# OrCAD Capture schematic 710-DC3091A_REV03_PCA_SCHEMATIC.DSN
size Custom; title: 5V, DUAL 6A SYNCHRONOUS STEP-DOWN REGULATOR
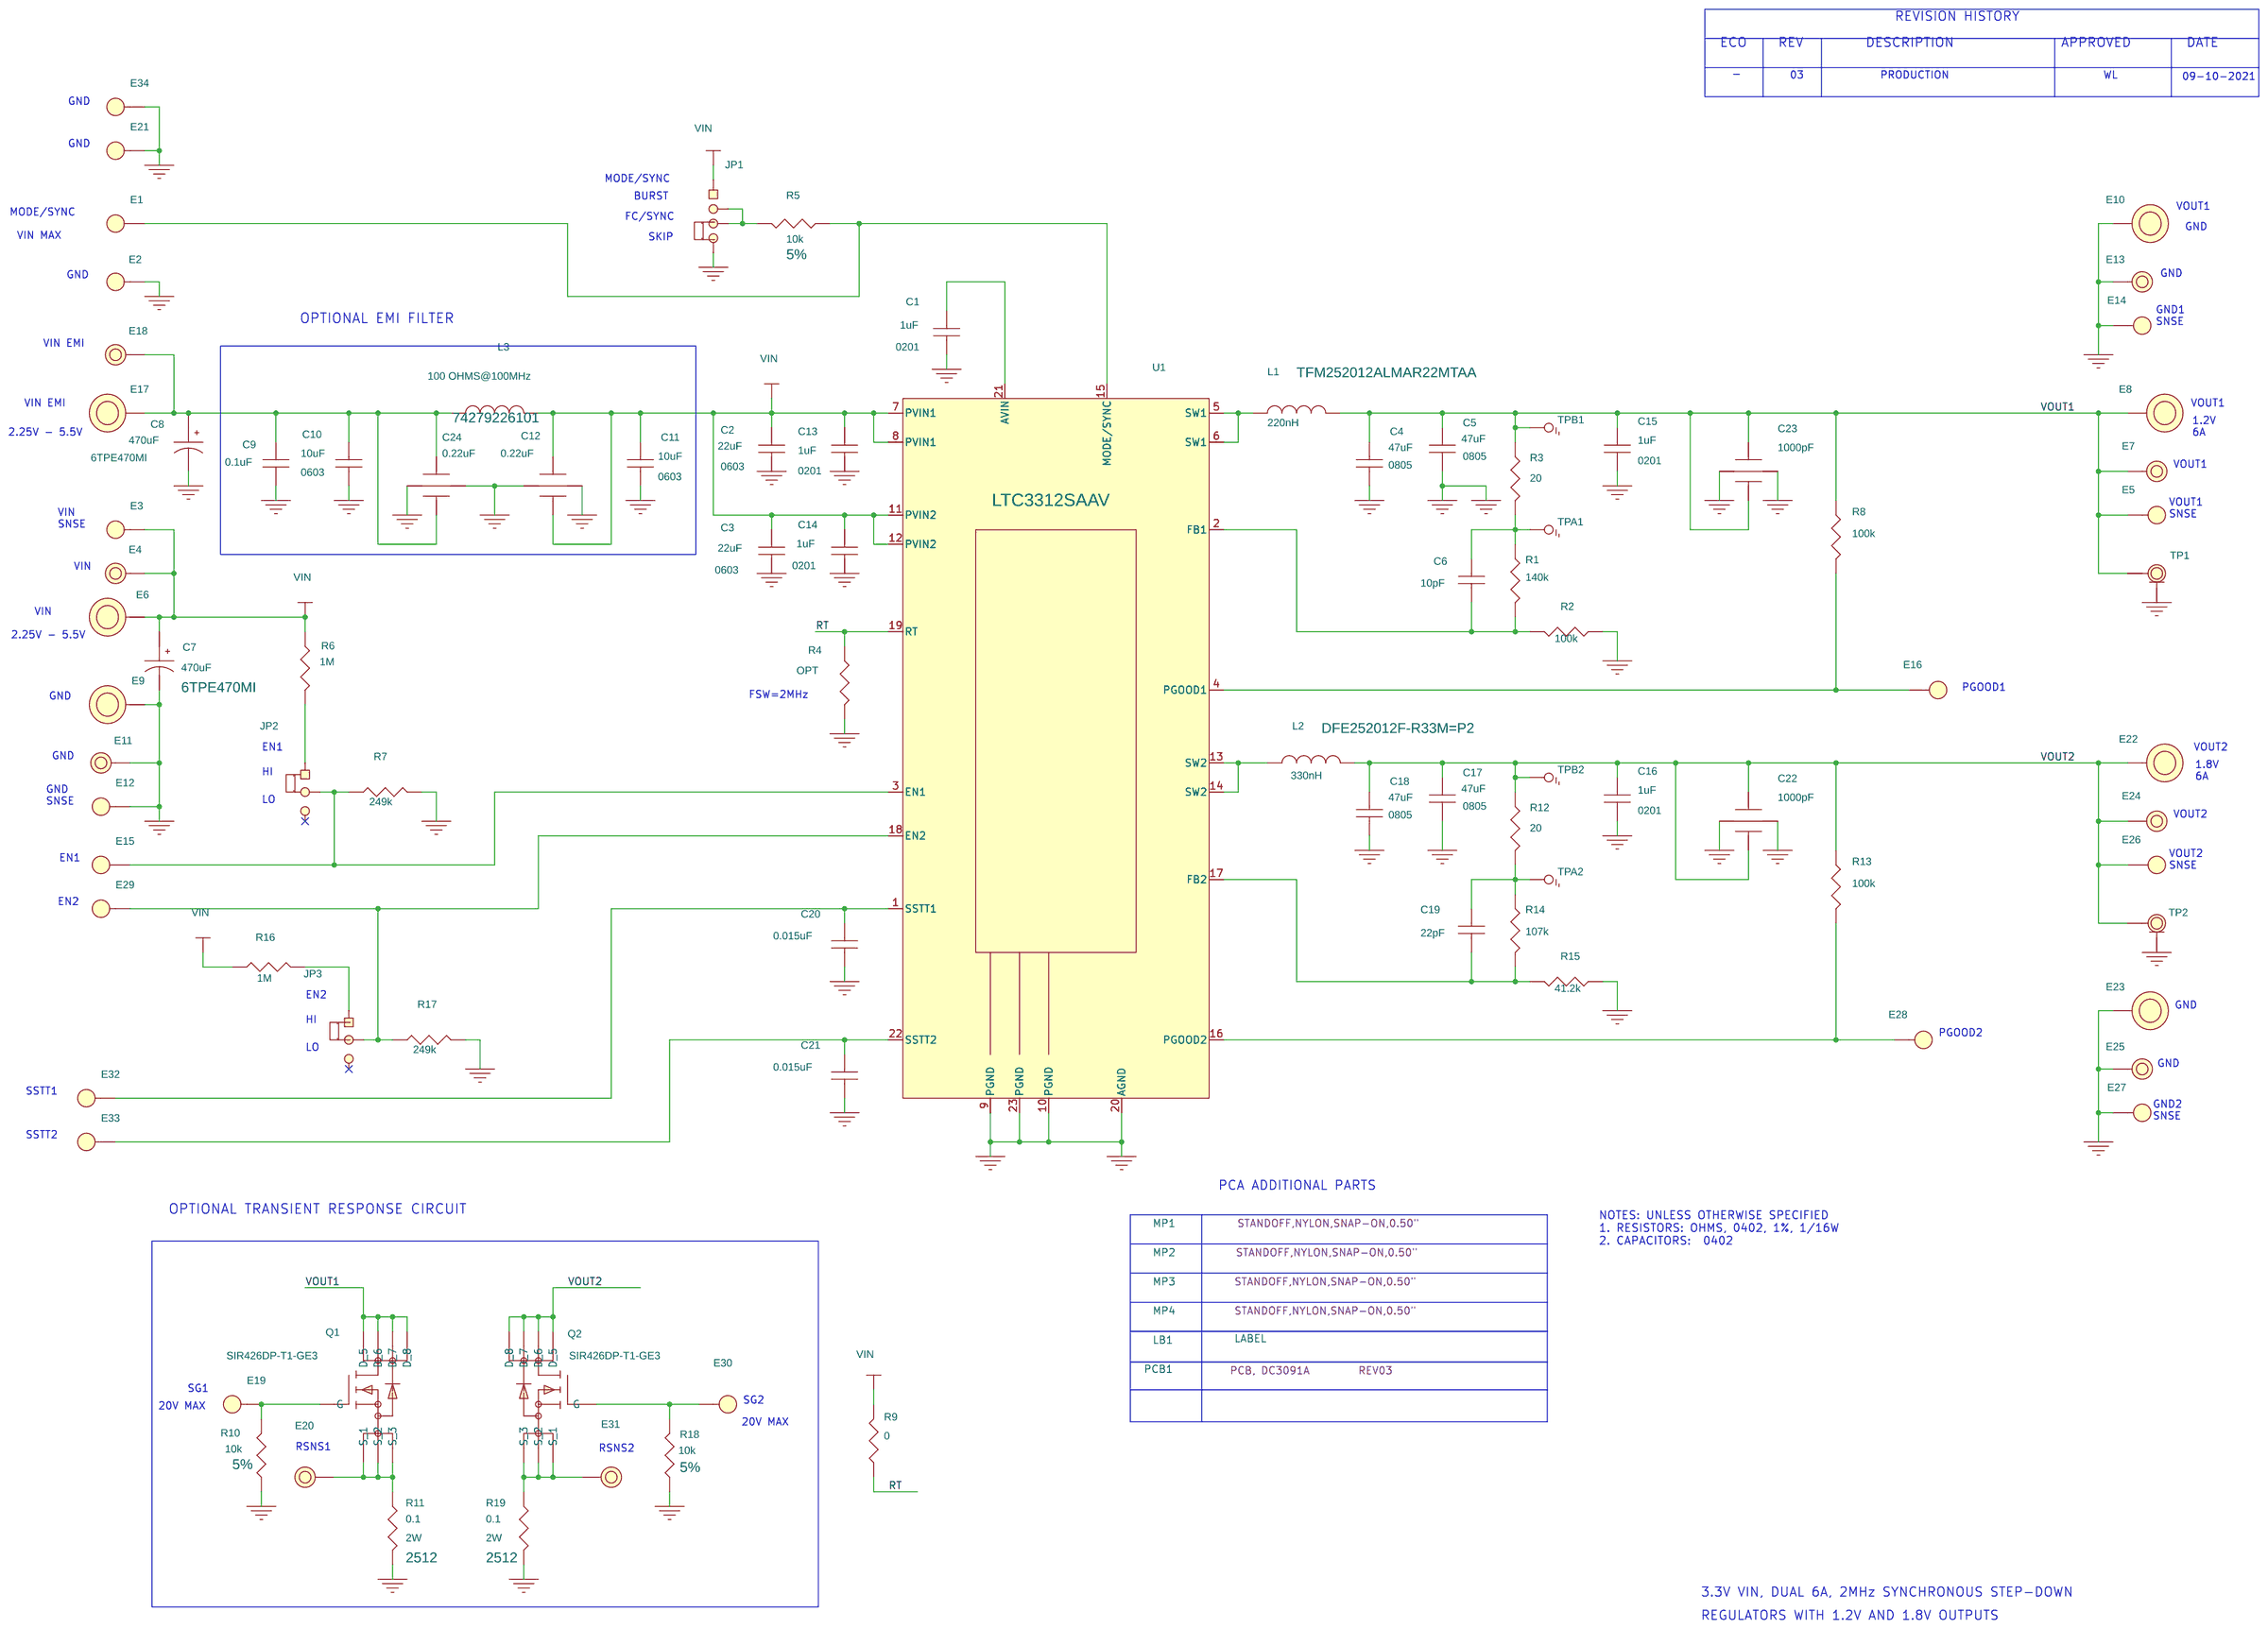
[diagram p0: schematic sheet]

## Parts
C1  1uF  [CC0201M]
C2  22uF  [CC0603N]
C3  22uF  [CC0603N]
C4  47uF  [CC0805L]
C5  47uF  [CC0805L]
C6  10pF  [CC0402N]
C7  470uF  [CAPMP7343N]
C8  470uF  [CAPMP7343N]
C9  0.1uF  [CC0402N]
C10  10uF  [CC0603N]
C11  10uF  [CC0603N]
C12  0.22uF  [JOHANSON-X2Y-X14]
C13  1uF  [CC0201M]
C14  1uF  [CC0201M]
C15  1uF  [CC0201M]
C16  1uF  [CC0201M]
C17  47uF  [CC0805L]
C18  47uF  [CC0805L]
C19  22pF  [CC0402N]
C20  0.015uF  [CC0402N]
C21  0.015uF  [CC0402N]
C22  1000pF  [JOHANSON-X2Y-X07]
C23  1000pF  [JOHANSON-X2Y-X07]
C24  0.22uF  [JOHANSON-X2Y-X14]
E1  TEST POINT  [MILLMAX2308]
E2  TEST POINT  [MILLMAX2308]
E3  TEST POINT  [MILLMAX2308]
E4  TEST POINT  [MILLMAX2501]
E5  TEST POINT  [MILLMAX2308]
E6  BANANA JACK  [KEY-575-4]
E7  TEST POINT  [MILLMAX2501]
E8  BANANA JACK  [KEY-575-4]
E9  BANANA JACK  [KEY-575-4]
E10  BANANA JACK  [KEY-575-4]
E11  TEST POINT  [MILLMAX2501]
E12  TEST POINT  [MILLMAX2308]
E13  TEST POINT  [MILLMAX2501]
E14  TEST POINT  [MILLMAX2308]
E15  TEST POINT  [MILLMAX2308]
E16  TEST POINT  [MILLMAX2308]
E17  BANANA JACK  [KEY-575-4]
E18  TEST POINT  [MILLMAX2501]
E19  TEST POINT  [MILLMAX2308]
E20  TEST POINT  [MILLMAX2501]
E21  TEST POINT  [MILLMAX2308]
E22  BANANA JACK  [KEY-575-4]
E23  BANANA JACK  [KEY-575-4]
E24  TEST POINT  [MILLMAX2501]
E25  TEST POINT  [MILLMAX2501]
E26  TEST POINT  [MILLMAX2308]
E27  TEST POINT  [MILLMAX2308]
E28  TEST POINT  [MILLMAX2308]
E29  TEST POINT  [MILLMAX2308]
E30  TEST POINT  [MILLMAX2308]
E31  TEST POINT  [MILLMAX2501]
E32  TEST POINT  [MILLMAX2308]
E33  TEST POINT  [MILLMAX2308]
E34  TEST POINT  [MILLMAX2308]
JP1  HDR  [JP4X1/079]
JP2  HDR  [HD1X3-079]
JP3  HDR  [HD1X3-079]
L1  220nH  [TDK-TFM252012ALMA]
L2  330nH  [MURATA-DFE252012F]
L3  100 OHMS@100MHz  [WURTH-74279226101]
LB1  LABEL  [895-0154_REV01]
MP1  STANDOFF  [KEYSTONE_8829-8834]
MP2  STANDOFF  [KEYSTONE_8829-8834]
MP3  STANDOFF  [KEYSTONE_8829-8834]
MP4  STANDOFF  [KEYSTONE_8829-8834]
PCB1  PCB, DC3091A
Q1  SIR426DP-T1-GE3  [VISHAY_PPAK_SO-8]
Q2  SIR426DP-T1-GE3  [VISHAY_PPAK_SO-8]
R1  140k  [CR0402N]
R2  100k  [CR0402N]
R3  20  [CR0402N]
R4  OPT  [CR0402N]
R5  10k  [CR0402N]
R6  1M  [CR0402N]
R7  249k  [CR0402N]
R8  100k  [CR0402N]
R9  0  [CR0402N]
R10  10k  [CR0402N]
R11  0.1  [CR2512N]
R12  20  [CR0402N]
R13  100k  [CR0402N]
R14  107k  [CR0402N]
R15  41.2k  [CR0402N]
R16  1M  [CR0402N]
R17  249k  [CR0402N]
R18  10k  [CR0402N]
R19  0.1  [CR2512N]
TP1  U.FL  [HIROSE-FL-R-SMT-1]
TP2  U.FL  [HIROSE-FL-R-SMT-1]
TPA1  COPPER FEATURE PAD  [PADSTYLE1]
TPA2  COPPER FEATURE PAD  [PADSTYLE1]
TPB1  COPPER FEATURE PAD  [PADSTYLE1]
TPB2  COPPER FEATURE PAD  [PADSTYLE1]
U1  LTC3312SAAV  [LTC-LQFN-22-7012]
XJP1  SHUNT
XJP2  SHUNT
XJP3  SHUNT

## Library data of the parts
C1 C13-C16 = CAP: CAP.,1uF,X7T,6.3V,20%,0201; CLASS: DISCRETE; Dielectric Type: X7T; FPLIST: CC0201N,CC0201L,CC0201M; Inventory Qty: 15600; Manufacturer: MURATA; Manufacturer PN: GRM033D70J105ME01D; PART_NUMBER: 150-1771; Package Size: 0201; Rated Voltage: 6.3V; Tolerance: 20%
C2 C3 = CAP: CAP.,22uF,X5R,10V,20%,0603; CLASS: DISCRETE; Dielectric Type: X5R; FPLIST: CC0603N,CC0603L,CC0603M; Inventory Qty: 29342; Manufacturer: AVX; Manufacturer PN: 0603ZD226MAT2A; PART_NUMBER: 150-2341; Package Size: 0603; Package Type: Surface Mount, MLCC; Rated Voltage: 10V; Temperature Coefficient: X5R; Tolerance: 20%
C4 C5 C17 C18 = CAP: CAP.,47uF,X6S,6.3V,20%,0805; CLASS: DISCRETE; Dielectric Type: X6S; FPLIST: CC0805L,CC0805N,CC0805M; Inventory Qty: 7800; Manufacturer: Taiyo Yuden; Manufacturer PN: JMK212BC6476MG-T; PART_NUMBER: 150-1772; Package Size: 0805; Rated Voltage: 6.3V; Temperature Coefficient: X6S; Tolerance: 20%
C6 = CAP: CAP.,10pF,C0G/NP0,50V,+/-0.5pF,0402; CLASS: DISCRETE; Dielectric Type: C0G/NP0; FPLIST: CC0402N,CC0402L,CC0402M; Inventory Qty: 24344; Manufacturer: AVX; Manufacturer PN: 04025A100DAT2A; PART_NUMBER: 150-2020; Package Size: 0402; Rated Voltage: 50V; Tolerance: +/-0.5pF
C7 C8 = CAP_P_ALT: CAP.,470uF,TANT,POSCAP,6.3V,20%,7343,18mOHMS,TPE; CLASS: DISCRETE; Dielectric Type: TANT,POSCAP; FPLIST: CAPMP7343N,CAPMP7343L,CAPMP7343M; Inventory Qty: 9794; Manufacturer: PANASONIC; Manufacturer PN: 6TPE470MI; PART_NUMBER: 150-0223; Package Size: 7343; Rated Voltage: 6.3V; Tolerance: 20%; UserField01: 2400mAms, 25mOHMS
C9 = CAP: CAP.,0.1uF,X7R,25V,10%,0402,AEC-Q200; CLASS: DISCRETE; Dielectric Type: X7R; FPLIST: CC0402N,CC0402L,CC0402M; Inventory Qty: 22030; Manufacturer: MURATA; Manufacturer PN: GCM155R71E104KE02D; PART_NUMBER: 150-1756; Package Size: 0402; Rated Voltage: 25V; Temperature Coefficient: X7R; Tolerance: 10%
C10 C11 = CAP: CAP.,10uF,X7S,6.3V,20%,0603; CLASS: DISCRETE; Dielectric Type: X7S; FPLIST: CC0603N,CC0603L,CC0603M; Inventory Qty: 34800; Manufacturer: TDK; Manufacturer PN: C1608X7S0J106M080AC; PART_NUMBER: 150-1745; Package Size: 0603; Rated Voltage: 6.3V; Tolerance: 20%
C12 C24 = JOHANSON-X2Y: CAP.,0.22uF,X7R,6.3V,20%,0603; CLASS: DISCRETE; Dielectric Type: X7R; Inventory Qty: 12000; Manufacturer: JOHANSON DIELECTRICS; Manufacturer PN: 6R3X14W224MV4T; PART_NUMBER: 150-0876; Package Size: 0603; Rated Voltage: 6.3V; Temperature Coefficient: X7R; Tolerance: 20%
C19 = CAP: CAP.,22pF,C0G,50V,10%,0402; CLASS: DISCRETE; Dielectric Type: C0G; FPLIST: CC0402N,CC0402L,CC0402M; Inventory Qty: 20000; Manufacturer: AVX; Manufacturer PN: 04025A220KAT2A; PART_NUMBER: 150-3390; Package Size: 0402; Rated Voltage: 50V; Tolerance: 10%
C20 C21 = CAP: CAP.,0.015uF,X7R,16V,10%,0402; CLASS: DISCRETE; Dielectric Type: X7R; FPLIST: CC0402N,CC0402L,CC0402M; Inventory Qty: 30000; Manufacturer: AVX; Manufacturer PN: 0402YC153KAT2A; PART_NUMBER: 150-2639; Package Size: 0402; Package Type: SMD; Rated Voltage: 16V; Tolerance: 10%
C22 C23 = JOHANSON-X2Y: CAP.,1000pF,X7R,50V,20%,0402,3-TERM,X2Y EMI FILTER; CLASS: DISCRETE; Dielectric Type: X7R; Inventory Qty: 16829; Manufacturer: JOHANSON DIELECTRICS; Manufacturer PN: 500X07W102MV4T; PART_NUMBER: 150-1785; Package Size: 0402,3-TERM; Rated Voltage: 50V; Tolerance: 20%
E1-E3 E5 E12 E14-E16 E19 E21 E26-E30 E32-E34 = TEST_POINT_.156_MILL-MAX_2308: TEST POINT,TURRET,0.064" MTG. HOLE,PCB 0.062" THK; CLASS: IO; Inventory Qty: 1142083; Manufacturer PN: 2308-2-00-80-00-00-07-0; PART_NUMBER: 260-0004
E4 E7 E11 E13 E18 E20 E24 E25 E31 = TESTPOINT_.219_MILL-MAX_2501: TEST POINT,TURRET,0.094" MTG. HOLE,PCB 0.062" THK; CLASS: IO; Inventory Qty: 823526; Manufacturer: MILL-MAX; Manufacturer PN: 2501-2-00-80-00-00-07-0; PART_NUMBER: 260-0003
E6 E8-E10 E17 E22 E23 = BANANA_KEYSTONE-575-4: CONN.,BANANA JACK,FEMALE,THT,NON-INSULATED,SWAGE,0.218"; CLASS: IO; Inventory Qty: 203061; Manufacturer: KEYSTONE; Manufacturer PN: 575-4; PART_NUMBER: 250-0428
JP1 = HD1X4-079_ALT: CONN.,HDR,MALE,1x4,2mm,VERT,ST,THT; CLASS: IO; Inventory Qty: 12591; Manufacturer: WURTH ELEKTRONIK; Manufacturer PN: 62000411121; PART_NUMBER: 250-0563
JP2 JP3 = 3_PIN_HEADER_.079_SINGLE_ROW_D: CONN.,HDR,MALE,1x3,2mm,VERT,ST,THT; CLASS: IO; Inventory Qty: 22026; Manufacturer: Wurth Elektronik; Manufacturer PN: 62000311121; PART_NUMBER: 250-0484
L1 = IND_ALT: IND.,220nH,PWR,20%,6.7A,13mOHMS,SMD,2.50mm x 2.00mm,AEC-Q200; CLASS: DISCRETE; Inventory Qty: 0; Manufacturer: TDK; Manufacturer PN: TFM252012ALMAR22MTAA; PART_NUMBER: 200-0414; Package Size: SMD,2.50mm x 2.00mm; Tolerance: 20%
L2 = IND_ALT: IND.,330nH,PWR,20%,5.1A,19mOHMS,1008; CLASS: DISCRETE; Inventory Qty: 3000; Manufacturer: MURATA; Manufacturer PN: DFE252012F-R33M=P2; PART_NUMBER: 200-0394; Package Size: 1008; Tolerance: 20%
L3 = IND_ALT: IND.,100 OHMS@100MHz,FERRITE BEAD,25%,8A,6mOHMS,1812; CLASS: DISCRETE; Inventory Qty: 3043; Manufacturer: WURTH ELEKTRONIK; Manufacturer PN: 74279226101; PART_NUMBER: 200-0280; Package Size: 1812; Tolerance: 25%
LB1 = BLANK_LABEL: LABEL SPEC, DEMO BOARD SERIAL NUMBER; Inventory Qty: 0; Manufacturer: BRADY; Manufacturer PN: THT-96-717-10; PART_NUMBER: 895-0154
MP1-MP4 = BLANK_MECHANICAL_PART: STANDOFF,NYLON,SNAP-ON,0.50"; CLASS: DISCRETE; FPLIST: KEYSTONE_8829-8834,MTG-8831; Inventory Qty: 9249; Manufacturer: WURTH ELEKTRONIK; Manufacturer PN: 702935000; PART_NUMBER: 763-0020
PCB1 = BLANK_PCB_PART: BOM Notes: REV03; CLASS: DISCRETE; Inventory Qty: 0; Manufacturer: ADI APPROVED SUPPLIER; Manufacturer PN: 600-DC3091A; PART_NUMBER: 600-DC3091A
Q1 Q2 = 8P_N-CH_TYPE1A: XSTR.,MOSFET,N-CH,40V,15.9A,PPAK SO-8; CLASS: DISCRETE; Inventory Qty: 20200; Manufacturer: VISHAY; PART_NUMBER: 240-0378; Package Size: PowerPAK® SO-8; Package Type: PPAK SO-8; Polarity: MOSFET N-Channel; Rated Power: 41.7W; Rated Voltage: 40V
R1 = RES: RES.,140k OHMS,1%,1/16W,0402,AEC-Q200; CLASS: DISCRETE; FPLIST: CR0402N,CR0402L,CR0402M; Inventory Qty: 70827; Manufacturer: NIC; Manufacturer PN: NRC04F1403TRF; PART_NUMBER: 100-2880; Package Size: 0402; Rated Power: 1/16W; Temperature Coefficient: 100ppm; Tolerance: 1%
R2 = RES: RES.,100k OHMS,1%,1/16W,0402,AEC-Q200; CLASS: DISCRETE; FPLIST: CR0402N,CR0402L,CR0402M; Inventory Qty: 150967; Manufacturer: VISHAY; Manufacturer PN: CRCW0402100KFKED; PART_NUMBER: 100-2396; Package Size: 0402; Rated Power: 1/16W; Temperature Coefficient: 100ppm; Tolerance: 1%
R3 R12 = RES: RES.,20 OHMS,1%,1/16W,0402,AEC-Q200; CLASS: DISCRETE; FPLIST: CR0402N,CR0402L,CR0402M; Inventory Qty: 29845; Manufacturer: NIC; Manufacturer PN: NRC04F20R0TRF; PART_NUMBER: 100-0250; Package Size: 0402; Rated Power: 1/16W; Temperature Coefficient: 100ppm; Tolerance: 1%
R4 = RES: RES., OPTION, 0402; CLASS: DISCRETE; FPLIST: CR0402N,CR0402L,CR0402M; PART_NUMBER: 100-0357; Package Size: 0402
R5 R10 R18 = RES: RES.,10k OHMS,5%,1/10W,0402,AEC-Q200; CLASS: DISCRETE; FPLIST: CR0402N,CR0402L,CR0402M; Inventory Qty: 33211; Manufacturer: PANASONIC; Manufacturer PN: ERJ2GEJ103X; PART_NUMBER: 100-0092; Package Size: 0402; Rated Power: 1/10W; Temperature Coefficient: 200ppm/C; Tolerance: 5%
R6 R16 = RES: RES.,1M OHM,1%,1/16W,0402,AEC-Q200; CLASS: DISCRETE; FPLIST: CR0402N,CR0402L,CR0402M; Inventory Qty: 86432; Manufacturer: STACKPOLE ELECTRONICS, INC.; Manufacturer PN: RMCF0402FT1M00; PART_NUMBER: 100-2457; Package Size: 0402; Rated Power: 1/16W; Temperature Coefficient: 100ppm; Tolerance: 1%
R7 R17 = RES: RES.,249k OHMS,1%,1/16W,0402,AEC-Q200; CLASS: DISCRETE; FPLIST: CR0402N,CR0402L,CR0402M; Inventory Qty: 26713; Manufacturer: NIC; Manufacturer PN: NRC04F2493TRF; PART_NUMBER: 100-2663; Package Size: 0402; Rated Power: 1/16W; Temperature Coefficient: 100ppm; Tolerance: 1%
R8 R13 = RES: RES.,100k OHMS,5%,1/16W,0402; CLASS: DISCRETE; FPLIST: CR0402N,CR0402L,CR0402M; Inventory Qty: 91623; Manufacturer: YAGEO; Manufacturer PN: RC0402JR-07100KL; PART_NUMBER: 100-0058; Package Size: 0402; Rated Power: 1/16W; Temperature Coefficient: 100ppm/C; Tolerance: 5%
R9 = RES: RES.,0 OHM,1/16W,0402; CLASS: DISCRETE; FPLIST: CR0402N,CR0402L,CR0402M; Inventory Qty: 264417; Manufacturer: ROHM; Manufacturer PN: MCR01MZPJ000; PART_NUMBER: 100-0215; Package Size: 0402; Rated Power: 1/16W
R11 R19 = RES: RES.,0.1 OHM,1%,2W,2512,SENSE,AEC-Q200; CLASS: DISCRETE; FPLIST: CR2512N,CR2512L,CR2512M; Inventory Qty: 9640; Manufacturer: TT ELECTRONICS; Manufacturer PN: LRC-LR2512LF-01-R100-F; PART_NUMBER: 100-0553; Package Size: 2512; Rated Power: 2W; Temperature Coefficient: 100ppm; Tolerance: 1%
R14 = RES: RES.,107k OHMS,1%,1/16W,0402,AEC-Q200; CLASS: DISCRETE; FPLIST: CR0402N,CR0402L,CR0402M; Inventory Qty: 19737; Manufacturer: NIC; Manufacturer PN: NRC04F1073TRF; PART_NUMBER: 100-2561; Package Size: 0402; Rated Power: 1/16W; Temperature Coefficient: +/-100ppm; Tolerance: 1%
R15 = RES: RES.,41.2k OHMS,1%,1/16W,0402,AEC-Q200; CLASS: DISCRETE; FPLIST: CR0402N,CR0402L,CR0402M; Inventory Qty: 25980; Manufacturer: VISHAY; Manufacturer PN: CRCW040241K2FKED; PART_NUMBER: 100-2706; Package Size: 0402; Rated Power: 1/16W; Temperature Coefficient: 100ppm/C; Tolerance: 1%
TP1 TP2 = HIROSE-U.FL-R-SMT-1_ALT1: CONN.,U.FL,RECEPT,ST SMD,0Hz to 6GHz 50Ohm; CLASS: IO; FPLIST: HIROSE-FL-R-SMT-1,HIROSE-FL-R-SMT-1_ALT1; Inventory Qty: 0; Manufacturer: HIROSE ELECTRIC; Manufacturer PN: U.FL-R-SMT-1(10); PART_NUMBER: 250-0939
TPA1 TPA2 TPB1 TPB2 = PAD_SMALL_FILLED: TESTPOINT, PCB COPPER FEATURE; CLASS: IO; Manufacturer: N/A; Manufacturer PN: N/A; PART_NUMBER: PCBPADS-11
U1 = LTC3312ASEV: IC,5V,DUAL 6A/DUAL PHASE 12A STEP-DOWN DC/DC REGULATOR,LQFN; CLASS: IC; Inventory Qty: 0; Manufacturer: ANALOG DEVICES; Manufacturer PN: LTC3312SAAV#PBF; PART_NUMBER: LTC3312SAAV#PBF; Package Size: 4x3x0.95mm; Package Type: LQFN
XJP1-XJP3 = CONN_SHUNT_2_POS_2mm: CONN.,SHUNT,FEMALE,2-POS,2mm; CLASS: IO; Inventory Qty: 64675; Manufacturer: Wurth Elektronik; Manufacturer PN: 60800213421; PART_NUMBER: 250-0485

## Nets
GND: C1.2 C2.2 C3.2 C4.2 C5.2 C7.2 C8.2 C9.2 C10.2 C11.2 C12.3(G1) C12.4(G2) C13.2 C14.2 C15.2 C16.2 C17.2 C18.2 C20.2 C21.2 C22.3(G1) C22.4(G2) C23.3(G1) C23.4(G2) C24.3(G1) C24.4(G2) E2.1(A) E9.1 E10.1 E11.1 E12.1(A) E13.1 E14.1(A) E21.1(A) E23.1 E25.1 E27.1(A) E34.1(A) JP1.4 R2.1 R4.2 R7.2 R10.2 R11.2 R15.1 R17.2 R18.2 R19.2 TP1.3(GND) TP2.3(GND) U1.9(PGND) U1.10(PGND) U1.20(AGND) U1.23(PGND)
VIN: C2.1 C3.1 C7.1 C11.1 C12.1(A) C12.2(B) C13.1 C14.1 E3.1(A) E4.1 E6.1 JP1.1 L3.2 R6.1 R9.2 R16.1 U1.7(PVIN1) U1.8(PVIN1) U1.11(PVIN2) U1.12(PVIN2)
RT: R4.1 R9.1 U1.19(RT)
VOUT1: C4.1 C5.1 C15.1 C23.1(A) C23.2(B) E5.1(A) E7.1 E8.1 L1.2 Q1.5(D) Q1.6(D) Q1.7(D) Q1.8(D) R3.1 R8.1 TP1.1 TPB1.1
VOUT2: C16.1 C17.1 C18.1 C22.1(A) C22.2(B) E22.1 E24.1 E26.1(A) L2.2 Q2.5(D) Q2.6(D) Q2.7(D) Q2.8(D) R12.1 R13.1 TP2.1 TPB2.1
N16763234: C6.2 R1.2 R2.2 U1.2(FB1)
N16763242: E15.1(A) JP2.2 R7.1 U1.3(EN1)
N16763412: C6.1 R1.1 R3.2 TPA1.1
N16763638: E16.1(A) R8.2 U1.4(PGOOD1)
N16763862: JP2.1 R6.2
N16780618: JP1.2 JP1.3 R5.1
N16799782: L1.1 U1.5(SW1) U1.6(SW1)
N16832261: E1.1(A) R5.2 U1.15(MODE/SYNC)
N16886451: C8.1 C9.1 C10.1 C24.1(A) C24.2(B) E17.1 E18.1 L3.1
N16918548: E19.1(A) Q1.4(G) R10.1
N16918561: E20.1 Q1.1(S) Q1.2(S) Q1.3(S) R11.1
N16941605: C19.1 R12.2 R14.1 TPA2.1
N16941624: C19.2 R14.2 R15.2 U1.17(FB2)
N16941661: E28.1(A) R13.2 U1.16(PGOOD2)
N16946210: L2.1 U1.13(SW2) U1.14(SW2)
N16947486: JP3.1 R16.2
N16947505: E29.1(A) JP3.2 R17.1 U1.18(EN2)
N16950373: C1.1 U1.21(AVIN)
N16953790: C20.1 E32.1(A) U1.1(SSTT1)
N16953814: C21.1 E33.1(A) U1.22(SSTT2)
N16959448: E30.1(A) Q2.4(G) R18.1
N16959463: E31.1 Q2.1(S) Q2.2(S) Q2.3(S) R19.1

Not connected (* = marked no-connect by the designer): JP2 3*; JP3 3*

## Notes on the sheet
- REVISION HISTORY
- ECO
- REV
- DESCRIPTION
- APPROVED
- DATE
- -
- 03
- PRODUCTION
- WL
- 09-10-2021
- GND
- GND
- MODE/SYNC
- BURST
- MODE/SYNC
- FC/SYNC
- VOUT1
- VIN MAX
- SKIP
- GND
- GND
- GND
- OPTIONAL EMI FILTER
- GND1
  SNSE
- VIN EMI
- VIN EMI
- VOUT1
- 1.2V
  6A
- 2.25V - 5.5V
- VOUT1
- VIN
  SNSE
- VOUT1
  SNSE
- VIN
- VIN
- 2.25V - 5.5V
- GND
- FSW=2MHz
- PGOOD1
- EN1
- VOUT2
- GND
- HI
- 1.8V
  6A
- GND
  SNSE
- LO
- VOUT2
- EN1
- VOUT2
  SNSE
- EN2
- EN2
- GND
- HI
- LO
- PGOOD2
- GND
- SSTT1
- GND2
  SNSE
- SSTT2
- PCA ADDITIONAL PARTS
- OPTIONAL TRANSIENT RESPONSE CIRCUIT
- NOTES: UNLESS OTHERWISE SPECIFIED
  1. RESISTORS: OHMS, 0402, 1%, 1/16W
  2. CAPACITORS:  0402
- SG1
- 20V MAX
- SG2
- 20V MAX
- RSNS1
- RSNS2
- 3.3V VIN, DUAL 6A, 2MHz SYNCHRONOUS STEP-DOWN
- REGULATORS WITH 1.2V AND 1.8V OUTPUTS
